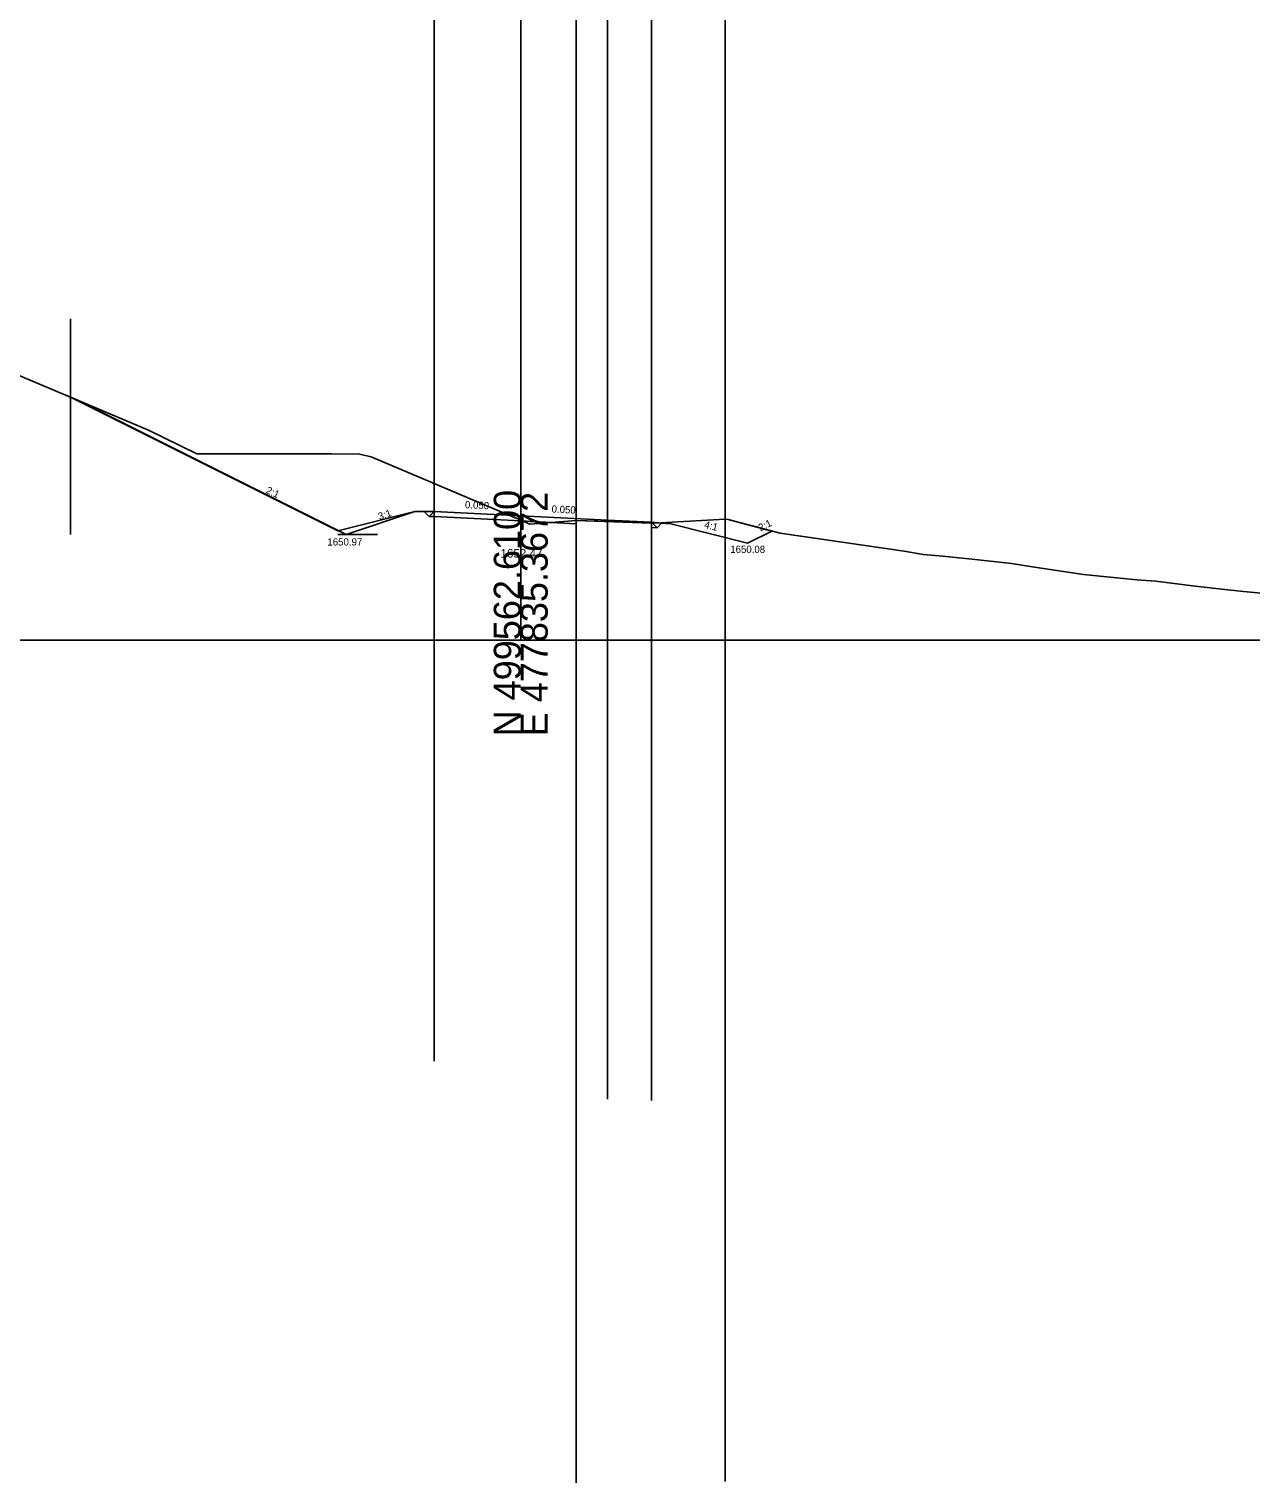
# Model space of a CAD drawing. Extents: x -26 to 403, y -99 to 4540.
# Drawn here: x 148.9 to 275.9, y 1412.4 to 1563.5 of the extents above; entities that cross this region are included whole.
import ezdxf

# ---------------------------------------------------------------- set-up
doc = ezdxf.new("R2010")
doc.units = 0
for name, color, linetype in [('Exist Cross Section Cell', 7, 'Continuous'), ('Exist XS Center Line Elevation Label', 7, 'Continuous'), ('Exist XS Ground Line', 7, 'Continuous'), ('Prop XS Ditch Slope Text', 7, 'Continuous'), ('Prop XS Ditch Standard Text', 7, 'Continuous'), ('Prop XS Dump Level', 7, 'Continuous'), ('Prop XS Earthwork Shape', 7, 'Continuous'), ('Prop XS EOT Tick Mark', 7, 'Continuous'), ('Prop XS Finish Grade', 7, 'Continuous'), ('Prop XS Finish Grade Earthwork', 7, 'Continuous'), ('Prop XS Finish Grade Paved Shoulder', 7, 'Continuous'), ('Prop XS Finish Grade Pavement', 7, 'Continuous'), ('Prop XS Hydro Typical Ditch Data', 7, 'Continuous'), ('Prop XS Pvmt Edge Slope', 7, 'Continuous'), ('Prop XS SE Text', 7, 'Continuous'), ('Prop XS Shoulder Borrow Shape', 7, 'Continuous'), ('Prop XS Side Slope Text', 7, 'Continuous'), ('Prop XS Subgrade Earthwork', 7, 'Continuous'), ('Scratch_Level_1', 7, 'Continuous'), ('Scratch_Level_2', 7, 'Continuous'), ('Scratch_Level_4', 7, 'Continuous'), ('Scratch_Level_6', 7, 'Continuous')]:
    doc.layers.add(name, color=color, linetype=linetype)

msp = doc.modelspace()

# ---------------------------------------------------------------- linework, layer by layer
at = {"layer": 'Exist Cross Section Cell'}
for p, q in [((200, 1500), (200, 1638.13)), ((0, 1500), (200, 1500)), ((200, 1500), (400, 1500))]:
    msp.add_line(p, q, dxfattribs=at)
at = {"layer": 'Exist XS Ground Line'}
msp.add_lwpolyline([(147.72, 1527.57), (161.31, 1521.81), (166.36, 1519.34), (180.36, 1519.35), (183.25, 1519.33), (184.47, 1519.03), (195.58, 1514.32), (200, 1512.47), (200.33, 1512.34), (200.95, 1512.03), (205.75, 1512.44), (212.6, 1512.18), (213.99, 1512.16), (215.1, 1512.22), (221.24, 1512.58), (221.57, 1512.53), (226.95, 1511.1), (239.83, 1509.24), (241.83, 1508.91), (243.48, 1508.75), (246.92, 1508.41), (250.98, 1507.96), (252.92, 1507.66), (258.48, 1506.83), (264.01, 1506.25), (265.98, 1506.12), (270.07, 1505.61), (273.47, 1505.22), (275.1, 1505.05), (280.97, 1504.51)], dxfattribs=at)
at = {"layer": 'Prop XS Dump Level'}
for p, q in [((191, 1513.37), (200, 1512.92)), ((200, 1512.92), (209, 1512.47))]:
    msp.add_line(p, q, dxfattribs=at)
at = {"layer": 'Prop XS Earthwork Shape'}
for points in [[(184.47, 1519.03), (195.58, 1514.32), (200, 1512.47), (200.26, 1512.36), (200, 1512.38), (191, 1512.83), (190.48, 1512.85), (189.98, 1513.36), (189, 1513.35), (181, 1511.35), (153.2, 1525.25), (161.31, 1521.81), (166.36, 1519.34), (180.36, 1519.35), (183.25, 1519.33)], [(200.33, 1512.34), (200.95, 1512.03), (203.16, 1512.22), (200.26, 1512.36)], [(205.75, 1512.09), (205.75, 1512.44), (203.16, 1512.22)], [(215.1, 1512.22), (221.24, 1512.58), (221.57, 1512.53), (226.08, 1511.33), (223.58, 1510.08), (215.58, 1512.08), (214.64, 1512.15), (214.16, 1511.67), (213.58, 1511.7), (213.58, 1512.17), (213.99, 1512.16)]]:
    msp.add_lwpolyline(points, close=True, dxfattribs=at)
at = {"layer": 'Prop XS EOT Tick Mark'}
for p, q in [((191, 1513.37), (191, 1514.37)), ((213.58, 1512.24), (213.58, 1513.24))]:
    msp.add_line(p, q, dxfattribs=at)
at = {"layer": 'Prop XS Finish Grade'}
for p, q in [((191, 1513.37), (189.98, 1513.36)), ((213.58, 1512.24), (214.64, 1512.15))]:
    msp.add_line(p, q, dxfattribs=at)
at = {"layer": 'Prop XS Finish Grade Earthwork'}
for p, q in [((181.86, 1510.97), (153.89, 1524.95)), ((189, 1513.35), (181.86, 1510.97)), ((189.98, 1513.36), (189, 1513.35)), ((214.64, 1512.15), (215.58, 1512.08)), ((215.58, 1512.08), (223.58, 1510.08)), ((223.58, 1510.08), (226.08, 1511.33))]:
    msp.add_line(p, q, dxfattribs=at)
at = {"layer": 'Prop XS Finish Grade Paved Shoulder'}
msp.add_line((209, 1512.47), (213.58, 1512.24), dxfattribs=at)
at = {"layer": 'Prop XS Finish Grade Pavement'}
for p, q in [((191, 1513.37), (200, 1512.92)), ((200, 1512.92), (209, 1512.47))]:
    msp.add_line(p, q, dxfattribs=at)
at = {"layer": 'Prop XS Hydro Typical Ditch Data'}
for p, q in [((189, 1513.35), (181.86, 1510.97)), ((215.58, 1512.08), (223.58, 1510.08)), ((223.58, 1510.08), (226.08, 1511.33))]:
    msp.add_line(p, q, dxfattribs=at)
at = {"layer": 'Prop XS Pvmt Edge Slope'}
for p, q in [((191, 1513.37), (190.48, 1512.85)), ((213.58, 1512.24), (214.16, 1511.67))]:
    msp.add_line(p, q, dxfattribs=at)
at = {"layer": 'Prop XS Shoulder Borrow Shape'}
for points in [[(191, 1513.37), (189.98, 1513.36), (190.48, 1512.85)], [(213.58, 1512.24), (214.64, 1512.15), (214.16, 1511.67)]]:
    msp.add_lwpolyline(points, close=True, dxfattribs=at)
at = {"layer": 'Prop XS Subgrade Earthwork'}
for p, q in [((190.48, 1512.85), (189.98, 1513.36)), ((191, 1512.83), (190.48, 1512.85)), ((200, 1512.38), (191, 1512.83)), ((205.75, 1512.09), (200, 1512.38)), ((205.75, 1512.09), (205.75, 1512.44)), ((213.58, 1512.17), (213.58, 1511.7)), ((214.16, 1511.67), (214.64, 1512.15)), ((213.58, 1511.7), (214.16, 1511.67))]:
    msp.add_line(p, q, dxfattribs=at)
at = {"layer": 'Scratch_Level_1'}
for p, q in [((205.75, 1612.44), (205.75, 1412.44)), ((221.24, 1612.58), (221.24, 1412.58))]:
    msp.add_line(p, q, dxfattribs=at)
at = {"layer": 'Scratch_Level_2'}
msp.add_line((213.58, 1562.17), (213.58, 1462.17), dxfattribs=at)
at = {"layer": 'Scratch_Level_4'}
for p, q in [((153.2, 1510.97), (153.2, 1533.39)), ((181, 1510.97), (185.11, 1510.97))]:
    msp.add_line(p, q, dxfattribs=at)
at = {"layer": 'Scratch_Level_6'}
for p, q in [((191, 1606.26), (191, 1456.26)), ((209, 1602.32), (209, 1452.32)), ((213.58, 1602.17), (213.58, 1452.17)), ((205.75, 1512.44), (213.58, 1512.17))]:
    msp.add_line(p, q, dxfattribs=at)

# ---------------------------------------------------------------- texts
at = {"layer": 'Exist Cross Section Cell'}
for s, p in [('N 499562.6100', (200, 1490)), ('E 477835.3672', (202.8, 1490))]:
    msp.add_text(s, height=2.8, rotation=90, dxfattribs=at).set_placement(p)
at = {"layer": 'Exist XS Center Line Elevation Label'}
msp.add_text('1652.47', height=0.9, dxfattribs=at).set_placement((197.9, 1508.57))
at = {"layer": 'Prop XS Ditch Slope Text'}
msp.add_text('4:1', height=0.75, rotation=345.9638, dxfattribs=at).set_placement((219.02, 1511.68))
at = {"layer": 'Prop XS Ditch Standard Text'}
for s, p in [('1650.97', (179.91, 1509.83)), ('1650.08', (221.77, 1509.06))]:
    msp.add_text(s, height=0.75, dxfattribs=at).set_placement(p)
at = {"layer": 'Prop XS Dump Level'}
for p in [(189, 1513.31), (215.58, 1512.04)]:
    msp.add_text('Case1', height=0.04, dxfattribs=at).set_placement(p)
at = {"layer": 'Prop XS SE Text'}
for p in [(194.19, 1513.71), (203.19, 1513.26)]:
    msp.add_text('0.050', height=0.75, rotation=357.1376, dxfattribs=at).set_placement(p)
at = {"layer": 'Prop XS Side Slope Text'}
for s, rotation, p in [('2:1', 335.5141, (173.45, 1515.31)), ('3:1', 18.5386, (185.32, 1512.46)), ('2:1', 26.5651, (224.92, 1511.29))]:
    msp.add_text(s, height=0.75, rotation=rotation, dxfattribs=at).set_placement(p)

doc.saveas('drawing.dxf')
